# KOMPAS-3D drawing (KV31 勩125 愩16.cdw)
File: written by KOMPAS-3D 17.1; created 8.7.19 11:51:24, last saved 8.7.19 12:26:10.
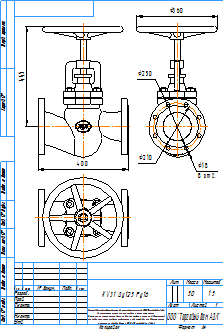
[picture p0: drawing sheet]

Sheet 1: A4, portrait

Title block, sheet 1: name: KV31 Ду125 Ру16; material: Сталь 10  ГОСТ 1050-88; mass: 50; sheets: 1; sheet format: A4

Views: Вид 1, Проекционный вид 2, Проекционный вид 3
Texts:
  kka
  adl
  Рама для чертежей
  Лит-Масса-Масштаб
  Материал-Предприятие
  Масштаб
  Изм.
  Лист
  № докум.
  Подп.
  Дата
  Лит.
  Разраб.
  Пров.
  Т.контр.
  Листов
  Внимание! Данный продукт является объектом авторского права ООО «Торговый Дом АДЛ».
  Запрещается изменение, копирование, распространение
  (в том числе путем копирования на другие сайты и ресурсы в Интернете)
  или любое иное использование информации и объектов без предварительного
  согласия правообладателя (ООО «Торговый Дом АДЛ»).
  Н.контр.
  Утв.
  ООО "Торговый дом АДЛ"
  Изменение
  Номер документа
  Подпись
  Обозначение документа
  Наименование изделия
  Масса изделия по ГОСТ 2.109-73
  Порядковый номер листа
  Общее количество листов в документе
  Характер работы, выполненной лицом, подписавшим документ
  Наименование или индекс предприятия, выпускающего документ
  Инв. № подл.
  Подп. и дата
  Взам. инв. №
  Инв. № дубл.
  Инвентарный номер подлинника по ГОСТ 2.501-68
  Подпись принявшего подлинник в отдел технической документации
  Инвентарный номер подлинника, взамен которого выпущен данный подлинник
  Инвентарный номер дубликата по ГОСТ 2.502-68
  Подпись принявшего дубликат в отдел технической документации
  Справ. №
  Перв. примен.
  Обозначение документа, взамен или на основании которого выпущен данный документ
  Обозначение документа, в котором впервые записан данный документ
  Подпись лица, копировавшего чертеж
  Обозначение формата листа
  !Рама для чертежа
Dimensions and other numbers on the sheet: 400; 445; 360; 210; 18; 8 отв.; 250; 1:5; 1; 50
